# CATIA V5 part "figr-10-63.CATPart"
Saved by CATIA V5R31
Part number: Part3
Bounding box of the stored display mesh (mm): x -76.186 to 89.68, y -206 to 106, z -21.666 to 136.547
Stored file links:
  D:\PROJECTS\Project 2021\US EDITION\CATIA V5 6R 2021\Resources\Part Files\c10_catia_v5_6r2021_prt\c10_catia_v5_6r2021_prt\figr-10-63.CATPart
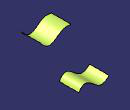
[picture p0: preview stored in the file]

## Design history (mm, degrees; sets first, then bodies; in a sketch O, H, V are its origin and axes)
Set1
  Plane1: type Offset, RefPlane zx-plane, Offset 100, reversed
  Sketch1 on Plane1, origin (0, -100, 0), H (-1, 0, 0), V (0, 0, 1)
    spline S1 through (-89.6797, 128.7958) (-21.8257, 98.6681) (14.6145, 123.4397) (76.1857, 133.4823)
  Extrude1: Element1 Sketch2, Lim1 106, Lim2 0, Direction zx-plane
  Extrude2: Element1 Sketch1, Lim1 106, Lim2 0, Direction Plane1
Body1 (main body)
  Sketch2 on zx-plane, origin (0, 0, 0), H (-1, 0, 0), V (0, 0, 1)
    spline S1 through (-88.2413, 0) (-57.9275, 26.3209) (-11.5211, 3.1904) (32.6399, -21.5353) (74.1811, 0)
    point P1 (-88.2413, 0)
    point P2 (74.1811, 0)
    coincidence: P1 H, P2 H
